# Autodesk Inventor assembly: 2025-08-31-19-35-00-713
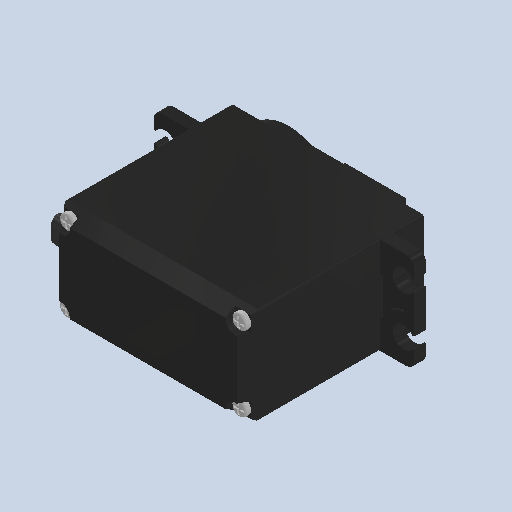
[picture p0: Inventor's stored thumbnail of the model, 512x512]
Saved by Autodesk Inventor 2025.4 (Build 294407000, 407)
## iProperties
Created: 2026-09
Part Number: 2025-08-31-19-35-00-713
Document SubType Name: Assembly
Designer: AdminForWorker
Title: MG995 v1
Author: AdminForWorker
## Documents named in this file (2)
- c:\worker\convert-fusion-r05-cosv3\tmp\job-1\19\temp\files\ca3d996b-dda0-445d-8bee-12a194174ca8\MG995 v1_1.iam
- c:\worker\convert-fusion-r05-cosv3\tmp\job-1\19\temp\files\ca3d996b-dda0-445d-8bee-12a194174ca8\Servo_1.iam
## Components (1 placed, 1 different names)
1. Servo:1 [sub-assembly]
